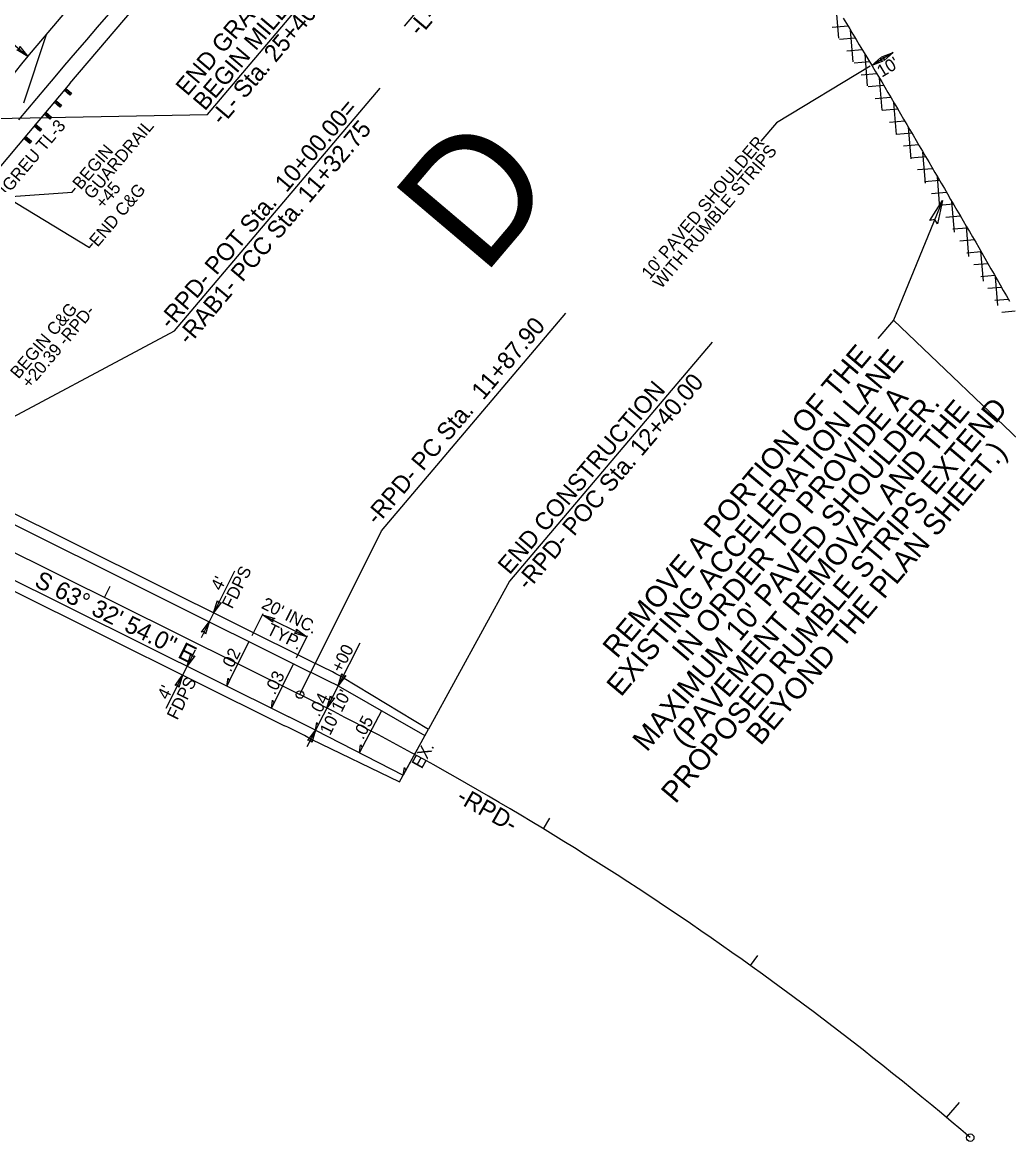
# Model space of a CAD drawing. Extents: x 1761082 to 1764358, y 421907 to 425434.
# Drawn here: x 1762337.6 to 1762735, y 422675.7 to 423126 of the extents above; entities that cross this region are included whole.
import ezdxf

# ---------------------------------------------------------------- set-up
doc = ezdxf.new("R2010")
doc.units = 0
for name, color, linetype in [('MARK HOOKS CENTER LEFT TURN ARROW CELL', 7, 'Continuous'), ('MARK HOOKS CENTER STRAIGHT LEFT TURN ARROW CELL', 7, 'Continuous'), ('MARK HOOKS STRAIGHT RIGHT TURN ARROW CELL', 7, 'Continuous'), ('MARK UTURN ARROW CELL', 7, 'Continuous'), ('Prop Conc 4in Sidewalk', 7, 'Continuous'), ('Prop Horizontal Alignment Tick Large', 7, 'Continuous'), ('Prop Mkg 3ft Min Skp 3ft Wide White', 7, 'Continuous'), ('Prop Mkg 3ft Min Skp 9ft Wide White', 7, 'Continuous'), ('Prop Mkg Min Skp 6ft Yellow', 7, 'Continuous'), ('Prop Mkg Skp Wht', 7, 'Continuous'), ('Prop Mkg Solid White Multiple Diagonals V8i', 7, 'Continuous'), ('Prop Mkg Solid White Stop Bar', 7, 'Continuous'), ('Prop Mkg Solid Yel Skip LT', 7, 'Continuous'), ('Prop Mkg Solid Yel Skip RT', 7, 'Continuous'), ('Prop Mkg Solid Yellow Lane Line', 7, 'Continuous'), ('Prop Mkg Yld Lin', 7, 'Continuous'), ('Scratch_Level_0', 7, 'Continuous'), ('Scratch_Level_5', 7, 'Continuous'), ('Typical Terminator CELL', 7, 'Continuous')]:
    doc.layers.add(name, color=color, linetype=linetype)

msp = doc.modelspace()

# ---------------------------------------------------------------- linework, layer by layer
at = {"layer": 'MARK HOOKS CENTER STRAIGHT LEFT TURN ARROW CELL'}
for p, q in [((1762370.78, 422894.21), (1762373.01, 422898.69)), ((1762460.29, 422849.62), (1762462.55, 422854.07)), ((1762547.61, 422800.94), (1762550.21, 422805.21)), ((1762631.02, 422745.81), (1762633.93, 422749.88))]:
    msp.add_line(p, q, dxfattribs=at)
at = {"layer": 'MARK UTURN ARROW CELL'}
for points in [[(1762491.66, 423124.36), (1762575.15, 423222.91), (1762482.79, 423313.42)], [(1762290.53, 423086.48), (1762412.19, 423088.84), (1762499.02, 423191.34)], [(1762317.87, 422958.33), (1762398.98, 423001.7), (1762481.78, 423099.43)], [(1762449.48, 422855.05), (1762482.31, 422921.03), (1762556.57, 423008.69)], [(1762615.56, 422997.11), (1762533.9, 422900.71), (1762501.25, 422841.16)]]:
    msp.add_lwpolyline(points, dxfattribs=at)
for centre in [(1762449.48, 422855.05), (1762719.56, 422676.49)]:
    msp.add_circle(centre, 1.5, dxfattribs=at)
at = {"layer": 'Prop Conc 4in Sidewalk'}
for p, q in [((1762666.59, 423119.51), (1762665.52, 423132.4)), ((1762670.36, 423124.37), (1762663.93, 423123.84)), ((1762672.39, 423110.06), (1762671.34, 423122.74)), ((1762673.24, 423119.59), (1762666.87, 423119.06)), ((1762676.12, 423114.81), (1762669.8, 423114.29)), ((1762678.21, 423100.34), (1762677.16, 423113.08)), ((1762678.99, 423110.03), (1762672.72, 423109.51)), ((1762681.87, 423105.25), (1762675.6, 423104.73)), ((1762684.04, 423090.52), (1762682.97, 423103.42)), ((1762684.74, 423100.47), (1762678.44, 423099.95)), ((1762687.59, 423095.69), (1762681.28, 423095.17)), ((1762690.41, 423090.91), (1762684.12, 423090.39)), ((1762689.87, 423080.71), (1762688.8, 423093.65)), ((1762693.21, 423086.12), (1762686.96, 423085.61)), ((1762696.01, 423081.34), (1762689.8, 423080.82)), ((1762695.7, 423070.89), (1762694.64, 423083.68)), ((1762698.81, 423076.55), (1762692.64, 423076.04)), ((1762701.62, 423071.77), (1762695.48, 423071.26)), ((1762701.53, 423061.08), (1762700.48, 423073.7)), ((1762704.42, 423066.98), (1762698.32, 423066.48)), ((1762707.36, 423051.25), (1762706.33, 423063.72)), ((1762707.22, 423062.2), (1762701.16, 423061.7)), ((1762710.02, 423057.41), (1762704, 423056.91)), ((1762713.19, 423041.39), (1762712.17, 423053.75)), ((1762712.82, 423052.63), (1762706.83, 423052.13)), ((1762715.63, 423047.84), (1762709.67, 423047.35)), ((1762718.43, 423043.06), (1762712.5, 423042.57)), ((1762719.02, 423031.54), (1762718.01, 423043.77)), ((1762721.23, 423038.27), (1762715.33, 423037.78)), ((1762724, 423033.48), (1762718.16, 423033)), ((1762724.86, 423021.69), (1762723.86, 423033.74)), ((1762726.74, 423028.69), (1762720.99, 423028.22)), ((1762729.46, 423023.9), (1762723.82, 423023.43)), ((1762730.69, 423011.82), (1762729.73, 423023.43)), ((1762732.19, 423019.11), (1762726.65, 423018.65)), ((1762734.91, 423014.32), (1762729.48, 423013.87)), ((1762737.63, 423009.53), (1762732.3, 423009.08))]:
    msp.add_line(p, q, dxfattribs=at)
at = {"layer": 'Prop Horizontal Alignment Tick Large'}
msp.add_line((1762710.03, 422684.56), (1762715.17, 422690.69), dxfattribs=at)
at = {"layer": 'Prop Mkg 3ft Min Skp 3ft Wide White'}
msp.add_line((1762281.25, 422938.75), (1762449.48, 422855.05), dxfattribs=at)
msp.add_arc((1761859.27, 421668.77), 1325, 49.51257, 63.54833, dxfattribs=at)
at = {"layer": 'Prop Mkg 3ft Min Skp 9ft Wide White'}
msp.add_line((1762356.81, 423101.28), (1762492.62, 423261.6), dxfattribs=at)
at = {"layer": 'Prop Mkg Min Skp 6ft Yellow'}
for p, q in [((1762434.52, 422887.63), (1762430.07, 422878.67)), ((1762434.33, 422887.25), (1762452.24, 422878.34)), ((1762452.43, 422878.72), (1762447.97, 422869.76))]:
    msp.add_line(p, q, dxfattribs=at)
at = {"layer": 'Prop Mkg Skp Wht'}
for p, q in [((1762291.81, 422944.67), (1762453.93, 422864.01)), ((1762312.12, 422912.23), (1762445.02, 422846.1)), ((1762464.82, 422858.53), (1762499.83, 422838.55)), ((1762455.75, 422840.7), (1762491.09, 422822.59)), ((1762489.62, 422819.91), (1762501.25, 422841.16))]:
    msp.add_line(p, q, dxfattribs=at)
for radius in [1335, 1315]:
    msp.add_arc((1761859.27, 421668.77), radius, 63.02514, 63.54833, dxfattribs=at)
at = {"layer": 'Prop Mkg Solid White Multiple Diagonals V8i'}
msp.add_arc((1761859.27, 421668.77), 1325, 49.51257, 63.54833, dxfattribs=at)
at = {"layer": 'Prop Mkg Solid White Stop Bar'}
for p, q in [((1762305.74, 422942.21), (1762455.72, 422867.59)), ((1762332.7, 422897.52), (1762443.24, 422842.52)), ((1762466.64, 422862.09), (1762501.25, 422841.16)), ((1762453.94, 422837.14), (1762489.62, 422819.91))]:
    msp.add_line(p, q, dxfattribs=at)
for points in [[(1762336.21, 423086.71), (1762339.85, 423091.02), (1762343.48, 423095.3), (1762347.08, 423099.56), (1762350.81, 423103.95), (1762354.8, 423108.65), (1762359.07, 423113.64), (1762363.6, 423118.93), (1762367.91, 423123.95), (1762374.31, 423131.46)], [(1762668.39, 423127.64), (1762669.68, 423125.5), (1762670.97, 423123.36), (1762672.26, 423121.22), (1762673.55, 423119.07), (1762674.84, 423116.93), (1762676.13, 423114.79), (1762677.42, 423112.65), (1762678.71, 423110.51), (1762680, 423108.37), (1762681.29, 423106.22), (1762682.57, 423104.08), (1762683.86, 423101.95), (1762685.14, 423099.82), (1762686.41, 423097.7), (1762687.66, 423095.57), (1762688.92, 423093.44), (1762690.18, 423091.29), (1762691.44, 423089.14), (1762692.71, 423086.98), (1762693.97, 423084.82), (1762695.23, 423082.67), (1762696.5, 423080.51), (1762697.76, 423078.35), (1762699.02, 423076.19), (1762700.29, 423074.04), (1762701.55, 423071.88), (1762702.81, 423069.72), (1762704.08, 423067.57), (1762705.34, 423065.41), (1762706.6, 423063.25), (1762707.87, 423061.09), (1762709.13, 423058.94), (1762710.39, 423056.78), (1762711.66, 423054.62), (1762712.92, 423052.47), (1762714.18, 423050.31), (1762715.44, 423048.15), (1762716.71, 423046), (1762717.97, 423043.84), (1762719.23, 423041.68), (1762720.49, 423039.53), (1762721.75, 423037.38), (1762722.99, 423035.25), (1762724.22, 423033.12), (1762725.44, 423030.97), (1762726.67, 423028.8), (1762727.91, 423026.63), (1762729.14, 423024.46), (1762730.38, 423022.29), (1762731.61, 423020.11), (1762732.85, 423017.94), (1762734.09, 423015.77), (1762735.32, 423013.59)]]:
    msp.add_lwpolyline(points, dxfattribs=at)
for radius in [1339, 1311]:
    msp.add_arc((1761859.27, 421668.77), radius, 63.02514, 63.54833, dxfattribs=at)
at = {"layer": 'Prop Mkg Solid Yel Skip RT'}
for p, q in [((1762329.97, 423120.66), (1762339.89, 423112.25)), ((1762688.43, 423113.75), (1762679.86, 423108.59)), ((1762688.61, 423005.9), (1762770.55, 422927.64)), ((1762423.07, 422904.84), (1762409.69, 422877.96)), ((1762473.57, 422875.72), (1762464.82, 422858.53)), ((1762407.2, 422872.96), (1762395.47, 422849.38)), ((1762455.75, 422840.7), (1762452.31, 422833.94))]:
    msp.add_line(p, q, dxfattribs=at)
for points in [[(1762679.28, 423108.24), (1762641.47, 423085.48), (1762635.24, 423078.12)], [(1762316.98, 423064.07), (1762364.62, 423035.25), (1762365.99, 423036.87)], [(1762326.85, 423061.12), (1762333.14, 423055.79), (1762357.69, 423057.56), (1762359.06, 423059.17)], [(1762708.38, 423054.14), (1762688.61, 423005.9), (1762682.37, 422998.54)]]:
    msp.add_lwpolyline(points, dxfattribs=at)
at = {"layer": 'Prop Mkg Solid Yellow Lane Line'}
for points in [[(1762336.56, 423116.22), (1762339.89, 423112.25), (1762335.39, 423114.88), (1762336.47, 423115.15)], [(1762683.98, 423112.02), (1762688.43, 423113.75), (1762684.81, 423110.59), (1762684.89, 423111.62)], [(1762684.31, 423110.32), (1762679.86, 423108.59), (1762683.48, 423111.74), (1762683.4, 423110.72)], [(1762417.78, 422892.15), (1762414.69, 422888), (1762416.21, 422892.99), (1762416.72, 422891.99)], [(1762438.51, 422884.19), (1762434.33, 422887.25), (1762439.33, 422885.77), (1762438.34, 422885.25)], [(1762409.85, 422880.24), (1762412.91, 422884.42), (1762411.43, 422879.42), (1762410.91, 422880.41)], [(1762448.06, 422881.4), (1762452.24, 422878.34), (1762447.24, 422879.81), (1762448.23, 422880.33)], [(1762407.09, 422870.66), (1762404, 422866.51), (1762405.52, 422871.5), (1762406.03, 422870.51)], [(1762399.15, 422858.76), (1762402.21, 422862.93), (1762400.74, 422857.93), (1762400.22, 422858.92)], [(1762467.92, 422862.68), (1762464.82, 422858.53), (1762466.34, 422863.51), (1762466.85, 422862.52)], [(1762463.38, 422853.76), (1762460.29, 422849.62), (1762461.81, 422854.6), (1762462.32, 422853.61)], [(1762452.65, 422836.55), (1762455.75, 422840.7), (1762454.23, 422835.72), (1762453.72, 422836.71)]]:
    msp.add_lwpolyline(points, close=True, dxfattribs=at)
at = {"layer": 'Prop Mkg Yld Lin'}
for p, q in [((1762356.81, 423101.28), (1762326.68, 423065.53)), ((1762355.17, 423099.34), (1762354.52, 423098.57)), ((1762354.52, 423098.57), (1762356.82, 423096.64)), ((1762354.52, 423098.57), (1762355.67, 423097.6)), ((1762356.32, 423098.37), (1762354.52, 423098.57)), ((1762355.17, 423099.34), (1762357.46, 423097.4)), ((1762355.67, 423097.6), (1762355.17, 423099.34)), ((1762356.32, 423098.37), (1762355.67, 423097.6)), ((1762356.82, 423096.64), (1762356.32, 423098.37)), ((1762350.46, 423093.75), (1762352.8, 423091.79)), ((1762352.27, 423093.53), (1762350.46, 423093.75)), ((1762351.11, 423094.52), (1762353.44, 423092.55)), ((1762351.11, 423094.52), (1762351.63, 423092.77)), ((1762355.67, 423097.6), (1762357.46, 423097.4)), ((1762357.46, 423097.4), (1762356.82, 423096.64)), ((1762347.05, 423089.7), (1762349.38, 423087.74)), ((1762347.05, 423089.7), (1762347.57, 423087.95)), ((1762352.27, 423093.53), (1762351.63, 423092.77)), ((1762351.63, 423092.77), (1762353.44, 423092.55)), ((1762352.8, 423091.79), (1762352.27, 423093.53)), ((1762353.44, 423092.55), (1762352.8, 423091.79)), ((1762342.98, 423084.88), (1762342.34, 423084.12)), ((1762342.98, 423084.88), (1762345.31, 423082.93)), ((1762342.98, 423084.88), (1762343.5, 423083.14)), ((1762346.4, 423088.93), (1762348.73, 423086.97)), ((1762348.21, 423088.72), (1762346.4, 423088.93)), ((1762348.21, 423088.72), (1762347.57, 423087.95)), ((1762347.57, 423087.95), (1762349.38, 423087.74)), ((1762348.73, 423086.97), (1762348.21, 423088.72)), ((1762349.38, 423087.74), (1762348.73, 423086.97)), ((1762342.34, 423084.12), (1762344.66, 423082.16)), ((1762344.15, 423083.9), (1762342.34, 423084.12)), ((1762344.15, 423083.9), (1762343.5, 423083.14)), ((1762343.5, 423083.14), (1762345.31, 423082.93)), ((1762344.66, 423082.16), (1762344.15, 423083.9)), ((1762345.31, 423082.93), (1762344.66, 423082.16)), ((1762338.28, 423079.3), (1762340.68, 423077.28)), ((1762340.12, 423079.05), (1762338.28, 423079.3)), ((1762338.92, 423080.06), (1762341.32, 423078.04)), ((1762338.92, 423080.06), (1762339.48, 423078.29)), ((1762340.12, 423079.05), (1762339.48, 423078.29)), ((1762339.48, 423078.29), (1762341.32, 423078.04)), ((1762340.68, 423077.28), (1762340.12, 423079.05)), ((1762341.32, 423078.04), (1762340.68, 423077.28))]:
    msp.add_line(p, q, dxfattribs=at)
at = {"layer": 'Scratch_Level_0'}
for p, q in [((1762339.89, 423112.25), (1762662.64, 423493.23)), ((1762347.2, 423120.88), (1762338.11, 423093.44))]:
    msp.add_line(p, q, dxfattribs=at)
msp.add_arc((1762568.79, 422918.34), 300, 139.7301, 152.0251, dxfattribs=at)
at = {"layer": 'Scratch_Level_5'}
for p, q in [((1762428.95, 422876.44), (1762420.04, 422858.53)), ((1762446.86, 422867.53), (1762437.95, 422849.62)), ((1762464.82, 422858.53), (1762455.75, 422840.7)), ((1762482.33, 422848.54), (1762473.42, 422831.65)), ((1762499.83, 422838.55), (1762491.09, 422822.59))]:
    msp.add_line(p, q, dxfattribs=at)
for points in [[(1762420.04, 422858.53), (1762420.49, 422861.66), (1762421.07, 422860.6)], [(1762437.95, 422849.62), (1762438.39, 422852.75), (1762438.98, 422851.69)], [(1762455.75, 422840.7), (1762456.22, 422843.83), (1762456.8, 422842.76)], [(1762473.42, 422831.65), (1762473.93, 422834.77), (1762474.5, 422833.69)], [(1762491.09, 422822.59), (1762491.65, 422825.7), (1762492.2, 422824.62)]]:
    msp.add_lwpolyline(points, close=True, dxfattribs=at)
at = {"layer": 'Typical Terminator CELL'}
msp.add_lwpolyline([(1762703.33, 423046.08), (1762708.38, 423054.14), (1762706.35, 423044.79), (1762705.26, 423046.53)], close=True, dxfattribs=at)

# ---------------------------------------------------------------- texts
at = {"layer": 'MARK HOOKS CENTER LEFT TURN ARROW CELL'}
msp.add_text('S 63%%d 32\' 54.0" E', height=7, rotation=333.5483, dxfattribs=at).set_placement((1762342.05, 422898.91))
at = {"layer": 'MARK HOOKS STRAIGHT RIGHT TURN ARROW CELL'}
msp.add_text('-RPD-', height=7, rotation=330.1985, dxfattribs=at).set_placement((1762512.09, 422812.11))
at = {"layer": 'MARK UTURN ARROW CELL'}
for s, p in [('BEGIN MILLING/RESURFACING', (1762411.16, 423089.99)), ('-L- Sta. 28+38.30', (1762497.83, 423119.95)), ('-L- Sta. 25+40.87', (1762418.16, 423084.06)), ('END GRADE', (1762404.16, 423095.92)), ('-RPD- POT Sta.  10+00.00=', (1762397.33, 423001.91)), ('-RAB1- PCC Sta. 11+32.75', (1762404.81, 422995.58)), ('-RPD- PC Sta.  11+87.90', (1762480.61, 422922.99)), ('END CONSTRUCTION', (1762533.93, 422903.05)), ('-RPD- POC Sta. 12+40.00', (1762541.41, 422896.72))]:
    msp.add_text(s, height=7, rotation=49.7301, dxfattribs=at).set_placement(p)
at = {"layer": 'Prop Mkg Min Skp 6ft Yellow'}
for s, rotation, p in [("20' INC.", 333.5483, (1762433.57, 422890.02)), ('TYP.', 333.5483, (1762435.66, 422879.59)), ('.02', 63.5483, (1762421.6, 422863.83)), ('.03', 63.5483, (1762439.36, 422854.63)), ('.04', 63.0251, (1762457.23, 422845.75)), ('.05', 62.1603, (1762474.94, 422836.6)), ('EX.', 61.2955, (1762498.58, 422824.83))]:
    msp.add_text(s, height=5, rotation=rotation, dxfattribs=at).set_placement(p)
at = {"layer": 'Prop Mkg Solid Yel Skip LT'}
for s, height, rotation, p in [('MONOLITHIC CONC. ISLAND', 5, 50.1302, (1762324.67, 423117.59)), ("10'", 5, 31.0505, (1762683.87, 423103.6)), ('GUARDRAIL', 5, 49.7301, (1762365.74, 423054.3)), ('D', 50, 49.7301, (1762523.14, 423023.03)), ('BEGIN', 5, 49.7301, (1762361.17, 423058.18)), ("10' PAVED SHOULDER", 5, 49.8913, (1762590.47, 423022.15)), ('WITH RUMBLE STRIPS', 5, 49.8913, (1762595.05, 423018.29)), ('END C&G', 5, 49.7301, (1762367.94, 423035.13)), ('+45', 5, 49.7301, (1762370.32, 423050.43)), ('BEGIN C&G', 5, 49.7301, (1762336.08, 422981.97)), ('+20.39 -RPD-', 5, 49.7301, (1762340.66, 422978.09)), ('REMOVE A PORTION OF THE', 8.5, 49.8913, (1762577.23, 422869.25)), ('EXISTING ACCELERATION LANE', 8.5, 49.8913, (1762578.8, 422853.82)), ('IN ORDER TO PROVIDE A', 8.5, 49.8913, (1762605.12, 422867.77)), ("MAXIMUM 10' PAVED SHOULDER.", 8.5, 49.8913, (1762589.25, 422831.63)), ('PROPOSED RUMBLE STRIPS EXTEND', 8.5, 49.8913, (1762600.79, 422810.74)), ('(PAVEMENT REMOVAL AND THE', 8.5, 49.8913, (1762605, 422833.03)), ('BEYOND THE PLAN SHEET.)', 8.5, 49.8913, (1762635.08, 422834.16)), ('FDPS', 5, 63.5483, (1762422.2, 422889.27)), ("4'", 5, 63.5483, (1762417.73, 422896.57)), ('+00', 5, 63.0251, (1762466.21, 422863.52)), ('FDPS', 5, 63.5483, (1762400.05, 422844.51)), ("4'", 5, 63.5483, (1762396.2, 422852.66)), ("10'", 5, 63.0251, (1762466.27, 422847.58)), ("10'", 5, 63.0251, (1762461.62, 422838.34))]:
    msp.add_text(s, height=height, rotation=rotation, dxfattribs=at).set_placement(p)
at = {"layer": 'Prop Mkg Yld Lin'}
msp.add_text('GREU TL-3', height=5, rotation=49.7301, dxfattribs=at).set_placement((1762332.81, 423057.45))

doc.saveas('drawing.dxf')
